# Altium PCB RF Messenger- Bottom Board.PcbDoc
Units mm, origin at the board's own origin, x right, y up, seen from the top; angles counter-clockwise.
Board outline 60 x 85 mm, 2 copper layers (Top Layer, Bottom Layer); 9 components, 32 nets, 88 pads, 3 vias.
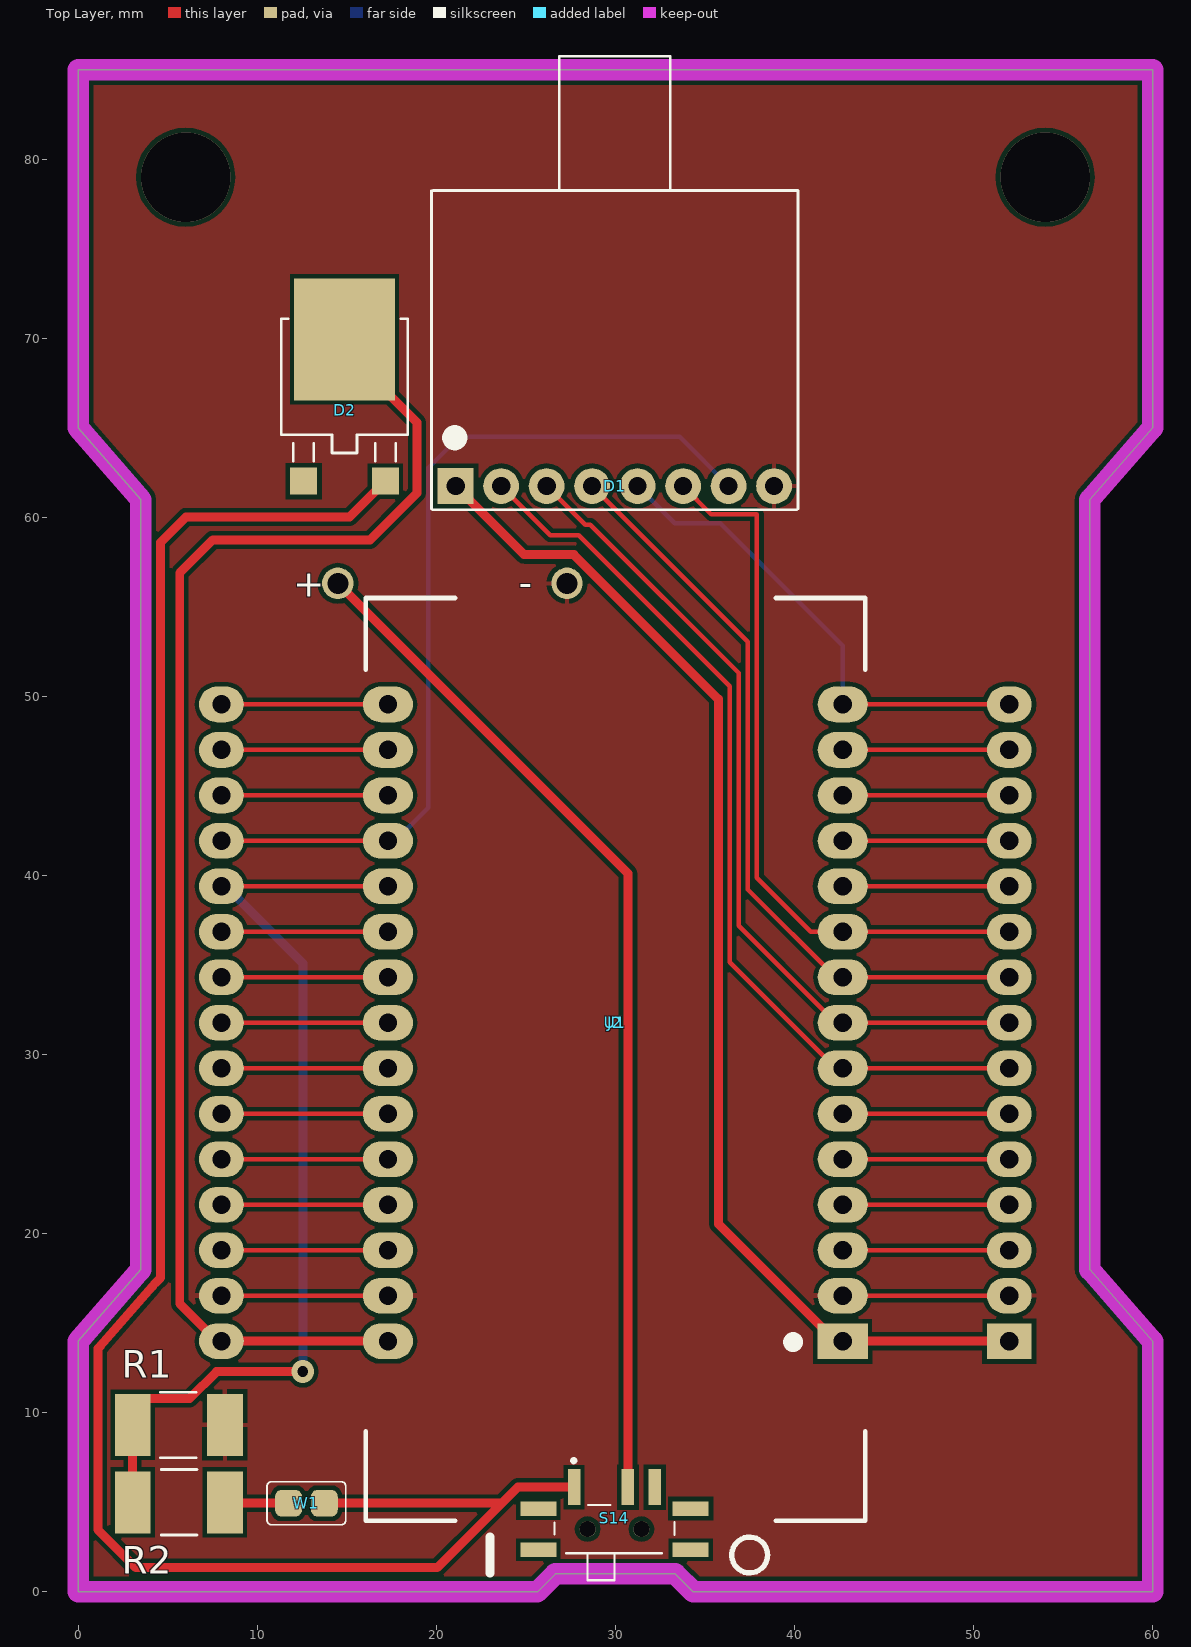
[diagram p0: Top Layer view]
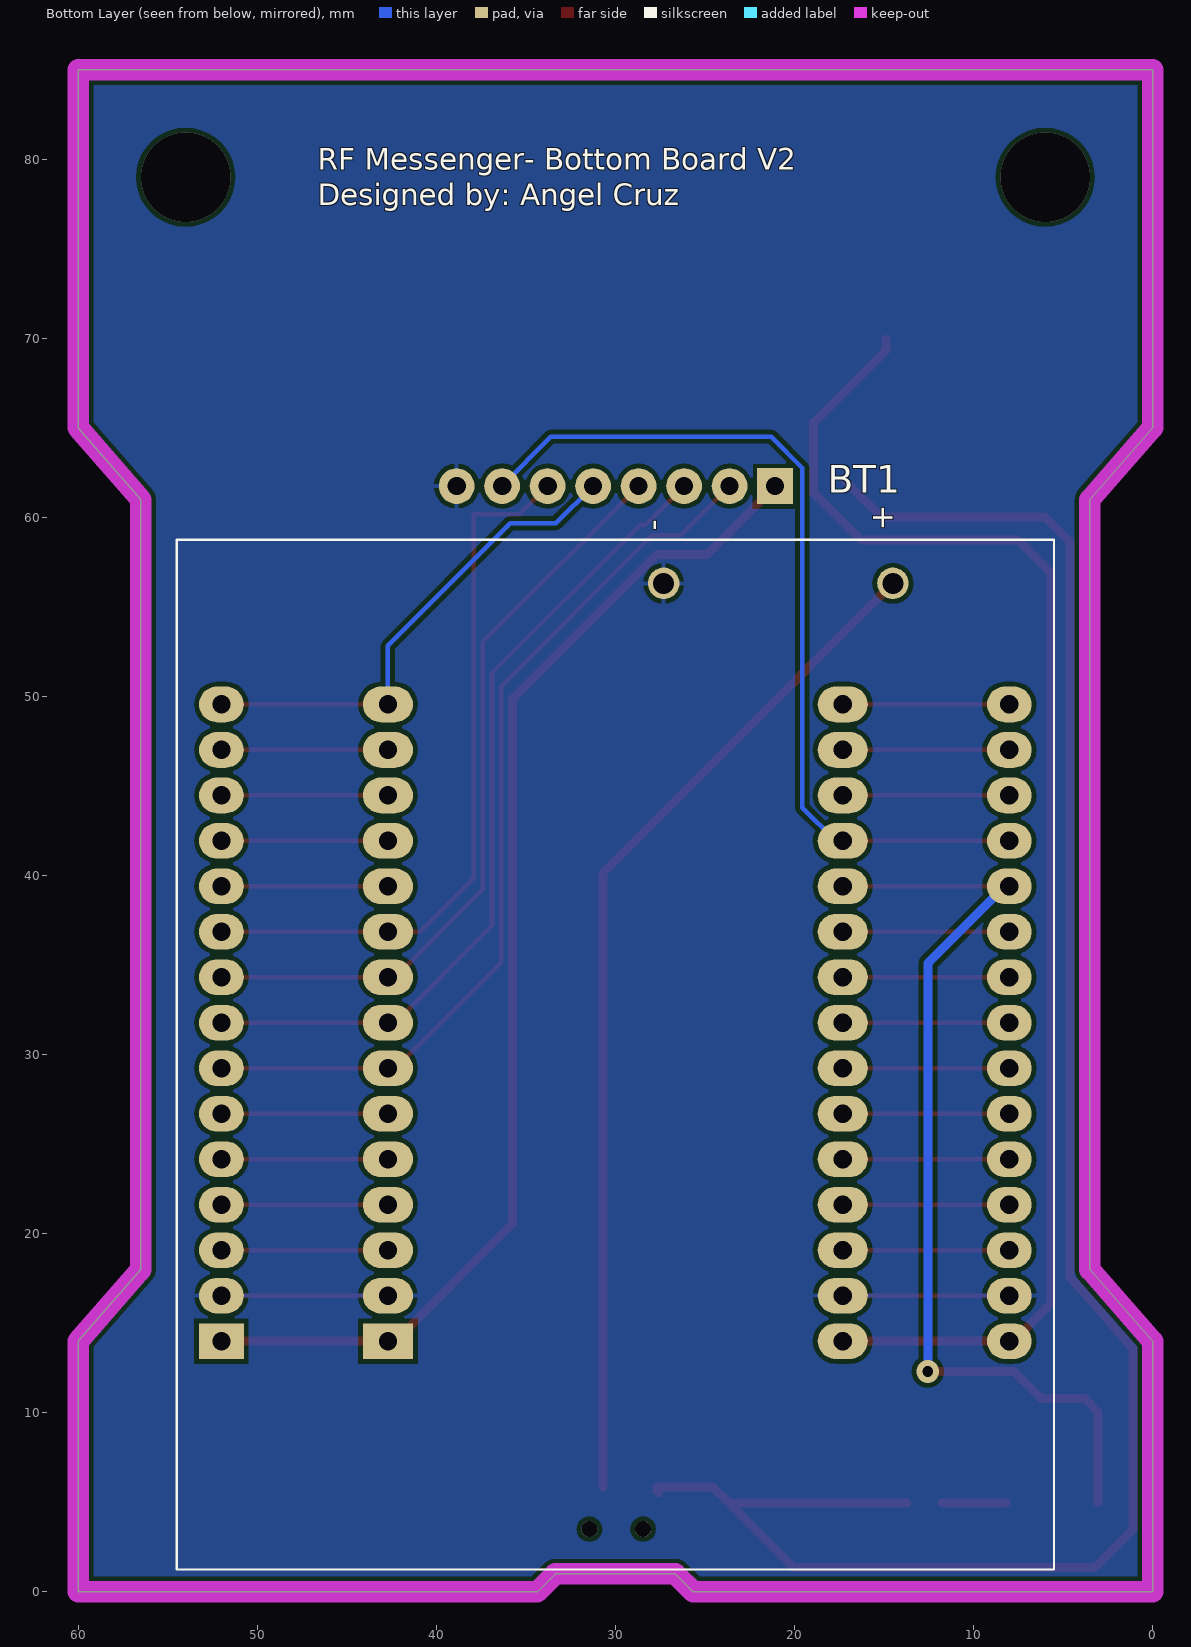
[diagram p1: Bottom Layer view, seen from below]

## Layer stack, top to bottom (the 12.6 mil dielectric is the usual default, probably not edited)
Top Solder: solder mask 0.0102, Solder Resist, Dk 3.5
Top Layer: signal copper 0.0356
Dielectric 1: dielectric 0.32, FR-4, Dk 4.8
Bottom Layer: signal copper 0.0356
Bottom Solder: solder mask 0.0102, Solder Resist, Dk 3.5

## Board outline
0,0 0,14 3.5,18 3.5,61 0,65 0,85 60,85 60,65 56.5,61 56.5,18 60,14 60,0 34.35,0 33.35,1 26.65,1 25.65,0

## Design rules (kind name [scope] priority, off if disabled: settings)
Clearance [All] p1: gap=0.254 ignorepadtopadclearanceinfootprint=FALSE except(0: Arc-Hole Track-Hole SMDPad-Hole THPad-Hole Via-Hole Fill-Hole Poly-Hole Region-Hole Text-Hole)
PolygonConnect [All] p1: connectstyle=Relief reliefconductorwidth=0.254 reliefentries=4 polygonreliefangle="90 Angle" airgapwidth=0.254
RoutingVias "RoutingVias 2" [All] p1: holewidth=0.4 width=0.8 viastyle="Through Hole" minholewidth=0.4 minwidth=0.8 maxholewidth=0.711 maxwidth=1.27
RoutingVias [All] p2: holewidth=0.711 width=1.27 viastyle="Through Hole" minholewidth=0.711 minwidth=1.27 maxholewidth=0.711 maxwidth=1.27
SolderMaskExpansion [All] p1: expansion=0.102 istentingtop=FALSE
Width [All] p1: maxlimit=0.5 minlimit=0.254 preferedwidth=0.254
30 further rules are at their usual default settings.

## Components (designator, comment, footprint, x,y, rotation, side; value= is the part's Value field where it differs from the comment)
BT1 "Battery" BAT_BC3AAPC 30,30 r90 bottom locked
D1 "NRF24L01+" WRL-00705 21.082,61.75 r0 top locked
D2 "25V, 5A" CSHD5-25L 14.875,67.85 r0 top
J2 "Connector 2x15" "RF Messenger Connector Headers - duplicate" 52,14 r0 top locked
R1 "10K" "Resistor 1812_PAN-M" 5.62,9.325 r0 top
R2 "10K" "Resistor 1812_PAN-M" 5.62,5 r180 top
S14 "Switch 2" "EG1257 Slide Switch" 29.95,3.5 r0 top locked
U1 "ESP-WROOM-32 Module" "ESP32 Dev Module" 42.7,14 r0 top locked
W1 "Jumper" JUMPER1.5x1.5 12.75,4.95 r180 top

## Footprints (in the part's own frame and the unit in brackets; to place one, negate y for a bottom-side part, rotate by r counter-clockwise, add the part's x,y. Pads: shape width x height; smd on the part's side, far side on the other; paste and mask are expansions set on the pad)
BAT_BC3AAPC [mm] "AA Battery Holder"
  round 1.755 hole 1.17: 1(26.32,-15.5) 2(26.32,-2.7)
  silkscreen extent -28.75,-24.5 28.75,24.5, body extent -28.75,-24.67 28.75,24.33, height 16.5
CSHD5-25L [mil] "SCHOTTKY RECTIFIER  5.0 AMP, 25 VOLT"
  rect 59.06x59.37 smd paste+0 mask+0: 1(90,-229.47) ""(-90,-229.47)
  rect 221x268 smd paste+0 mask+0: 2(0,82.5)
  silkscreen extent -139,-186 139,128, body extent -134,-238 134,186, height 108
"EG1257 Slide Switch" [mm] "Surface Mount Right Angle Slide Switch"
  rect 0.7x2 smd: 1(-2.25,2.35) 2(0.75,2.35) 3(2.25,2.35)
  rect 2x0.8 smd: ""(-4.25,-1.15) ""(-4.25,1.15) ""(4.25,-1.15) ""(4.25,1.15)
  round 0.9 hole 0.9 unplated: ""(-1.5,0) ""(1.5,0)
  silkscreen extent -3.35,-2.85 3.35,3.92, body extent -3.85,-2.85 3.85,2.25, height 1.5
"ESP32 Dev Module" [mm]
  rect 2.8x2 hole 1.02: 1(0,0)
  oval 2.8x2 hole 1.02: 2(0,2.54) 3(0,5.08) 4(0,7.62) 5(0,10.16) 6(0,12.7) 7(0,15.24) 8(0,17.78) 9(0,20.32) 10(0,22.86) 11(0,25.4) 12(0,27.94) 13(0,30.48) 14(0,33.02) 15(0,35.56) 16(-25.4,35.56) 17(-25.4,33.02) 18(-25.4,30.48) 19(-25.4,27.94) 20(-25.4,25.4) 21(-25.4,22.86) 22(-25.4,20.32) 23(-25.4,17.78) 24(-25.4,15.24) 25(-25.4,12.7) 26(-25.4,10.16) 27(-25.4,7.62) 28(-25.4,5.08) 29(-25.4,2.54) 30(-25.4,0)
  silkscreen extent -26.65,-10.02 1.25,41.5
JUMPER1.5x1.5 [mm] "1.5mmx1.5mm pads with .5mm gap"
  rrect50% 1.5x1.5 smd: 1(-1,0) 2(1,0)
  silkscreen extent -2.2,-1.2 2.2,1.2
"Resistor 1812_PAN-M" [mm]
  rect 2x3.454 smd paste+0 mask+0: 1(-2.573,0) 2(2.573,0)
  silkscreen extent -1.02,-1.83 0.98,1.83, body extent 0,0 0.25,0.25, height 0.25
"RF Messenger Connector Headers - duplicate" [mm] "Connector headers to connect top and bottom boards"
  rect 2.5x2 hole 1.02: 1(0,0)
  oval 2.5x2 hole 1.02: 2(0,2.54) 3(0,5.08) 4(0,7.62) 5(0,10.16) 6(0,12.7) 7(0,15.24) 8(0,17.78) 9(0,20.32) 10(0,22.86) 11(0,25.4) 12(0,27.94) 13(0,30.48) 14(0,33.02) 15(0,35.56) 16(-44,35.56) 17(-44,33.02) 18(-44,30.48) 19(-44,27.94) 20(-44,25.4) 21(-44,22.86) 22(-44,20.32) 23(-44,17.78) 24(-44,15.24) 25(-44,12.7) 26(-44,10.16) 27(-44,7.62) 28(-44,5.08) 29(-44,2.54) 30(-44,0)
WRL-00705 [mm]
  round 2 hole 1.02: 1(17.78,0) 3(2.54,0) 4(5.08,0) 5(7.62,0) 6(10.16,0) 7(12.7,0) 8(15.24,0)
  rect 2x2 hole 1.02: 2(0,0)
  silkscreen extent -1.35,-1.33 19.12,24.01

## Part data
BT1: "General Battery"
D1: "Radio module"
D2: library part "Diode - Schottky", "Generic Schottky Diode"
J2: "15 Pin Connector"
R1 R2: library part Resistor, "Resistor"
S14: "General Slide Switch"
U1: "ESP32 module THT"
W1: "Jumper Wire"

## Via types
v1: diameter 5, hole 5, Top Layer to Bottom Layer, 2 vias
v2: diameter 1.27, hole 0.6, Top Layer to Bottom Layer, 1 vias

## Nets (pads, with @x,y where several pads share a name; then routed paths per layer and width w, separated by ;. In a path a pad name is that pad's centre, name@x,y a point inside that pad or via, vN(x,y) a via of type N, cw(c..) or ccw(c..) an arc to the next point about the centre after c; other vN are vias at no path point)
GND: BT1.2 D1.1 J2.2 J2.29 R1.2 U1.2 U1.29 | length 18.6
  Top Layer w0.254: J2.29 U1.29 ; U1.2 J2.2
NetBT1_1: BT1.1 S14.2 | length 57.3
  Top Layer w0.5: BT1.1@14.5,56.406 BT1.1 30.7,40.12 S14.2
NetD1_2: D1.2 J2.1 U1.1 | length 67.9
  Top Layer w0.5: D1.2 24.907,57.925 27.681,57.925 35.75,49.856 35.75,20.55 42.3,14 U1.1 J2.1
NetD1_3: D1.3 J2.7 U1.7 | length 50.9
  Top Layer w0.254: D1.3 26.372,59 27.95,59 36.381,50.569 36.381,35.159 42.3,29.24 U1.7 J2.7
NetD1_4: D1.4 J2.8 U1.8 | length 46.5
  Top Layer w0.254: D1.4 28.311,59.601 28.599,59.601 36.889,51.311 36.889,37.191 42.3,31.78 U1.8 J2.8
NetD1_5: D1.5 J2.9 U1.9 | length 42.8
  Top Layer w0.254: D1.5 37.397,53.055 37.397,39.223 42.3,34.32 U1.9 J2.9
NetD1_6: D1.6 J2.15 U1.15 | length 27.7
  Top Layer w0.254: U1.15 J2.15
  Bottom Layer w0.254: D1.6 33.326,59.666 35.866,59.666 42.7,52.832 U1.15
NetD1_7: D1.7 J2.10 U1.10 | length 40.4
  Top Layer w0.254: D1.7 35.365,60.167 37.905,60.167 37.905,39.874 40.919,36.86 U1.10 J2.10
NetD1_8: D1.8 J2.19 U1.19 | length 49.9
  Top Layer w0.254: J2.19 U1.19 U1.19@17.7,41.94
  Bottom Layer w0.254: U1.19@17.7,41.94 19.556,43.796 19.556,62.763 21.293,64.5 33.6,64.5 36.322,61.778 D1.8
NetD2_1: D2.1 S14.1 W1.1 | length 110.1
  Top Layer w0.5: W1.1 23.65,4.95 ; D2.1 17.161,62.018 16.661,61.517 16.657,61.517 15.165,60.025 6.025,60.025 4.604,58.604 4.604,17.543 4.307,17.245 4.141,17.056 1.239,13.739 1.104,13.585 1.104,3.471 3.225,1.35 20.05,1.35 23.65,4.95 ; S14.1@27.6,5.554 27.7,5.654 S14.1@27.504,5.85 ; S14.1 S14.1@27.504,5.85 ; 23.65,4.95 24.55,5.85 S14.1@27.504,5.85
NetD2_2: D2.2 J2.30 U1.30 | length 78.4
  Top Layer w0.5: J2.30@7.775,14 5.675,16.1 5.675,56.9 7.525,58.75 16.3,58.75 18.925,61.375 18.925,65.299 14.875,69.349 D2.2 ; J2.30 U1.30
NetJ2_3: J2.3 U1.3 | length 9.3
  Top Layer w0.254: U1.3 J2.3
NetJ2_4: J2.4 U1.4 | length 9.3
  Top Layer w0.254: U1.4 J2.4
NetJ2_5: J2.5 U1.5 | length 9.3
  Top Layer w0.254: U1.5 J2.5
NetJ2_6: J2.6 U1.6 | length 9.3
  Top Layer w0.254: U1.6 J2.6
NetJ2_11: J2.11 U1.11 | length 9.3
  Top Layer w0.254: U1.11 J2.11
NetJ2_12: J2.12 U1.12 | length 9.3
  Top Layer w0.254: U1.12 J2.12
NetJ2_13: J2.13 U1.13 | length 9.3
  Top Layer w0.254: U1.13 J2.13
NetJ2_14: J2.14 U1.14 | length 9.3
  Top Layer w0.254: U1.14 J2.14
NetJ2_16: J2.16 U1.16 | length 9.3
  Top Layer w0.254: J2.16 U1.16
NetJ2_17: J2.17 U1.17 | length 9.3
  Top Layer w0.254: J2.17 U1.17
NetJ2_18: J2.18 U1.18 | length 9.3
  Top Layer w0.254: J2.18 U1.18
NetJ2_20: J2.20 R1.1 R2.2 U1.20 | length 53.9
  Top Layer w0.254: J2.20 U1.20
  Top Layer w0.5: R2.2 R1.1 3.047,10.052 3.797,10.802 6.231,10.802 7.729,12.3 v2(12.55,12.3)
  Bottom Layer w0.5: J2.20 8.25,39.4 12.55,35.1 v2(12.55,12.3)
NetJ2_21: J2.21 U1.21 | length 9.3
  Top Layer w0.254: J2.21 U1.21
NetJ2_22: J2.22 U1.22 | length 9.3
  Top Layer w0.254: J2.22 U1.22
NetJ2_23: J2.23 U1.23 | length 9.3
  Top Layer w0.254: J2.23 U1.23
NetJ2_24: J2.24 U1.24 | length 9.3
  Top Layer w0.254: J2.24 U1.24
NetJ2_25: J2.25 U1.25 | length 9.3
  Top Layer w0.254: J2.25 U1.25
NetJ2_26: J2.26 U1.26 | length 9.3
  Top Layer w0.254: J2.26 U1.26
NetJ2_27: J2.27 U1.27 | length 9.3
  Top Layer w0.254: J2.27 U1.27
NetJ2_28: J2.28 U1.28 | length 9.3
  Top Layer w0.254: J2.28 U1.28
NetR2_1: R2.1 W1.2 | length 3.6
  Top Layer w0.5: R2.1 8.244,4.95 W1.2
pads on no net: D2. S14. S14.3
copper on no net:
  other v1: 6,79 54,79

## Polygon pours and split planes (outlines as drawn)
GND on Bottom Layer "GND_L02_P000" (solid, pour order 0): 0,0 0,14 3.5,18 3.5,61 0,65 0,85 60,85 60,65 56.5,61 56.5,18 60,14 60,0 34.35,0 33.35,1 26.65,1 25.65,0
GND on Top Layer "GND_L01_P001" (solid, pour order 1): 0,0 0,14 3.5,18 3.5,61 0,65 0,85 60,85 60,65 56.5,61 56.5,18 60,14 60,0 34.35,0 33.35,1 26.65,1 25.65,0

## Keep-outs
Keep-Out Layer:
  the board outline again, w1.2

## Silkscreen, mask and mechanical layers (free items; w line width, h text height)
Top Overlay:
  circle w0.3: c37.5,2.058 r1
  lines w0.5: 23,1.058 23,3.058
  text "-" at 24.604,55.592 h1.52
  text "+" at 12.004,55.575 h1.52
Bottom Overlay:
  text "RF Messenger- Bottom Board V2" at 46.621,79.429 h1.2
  text "Designed by: Angel Cruz" at 46.621,77.429 h1.2
Mechanical 1:
  the board outline again, w0.1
